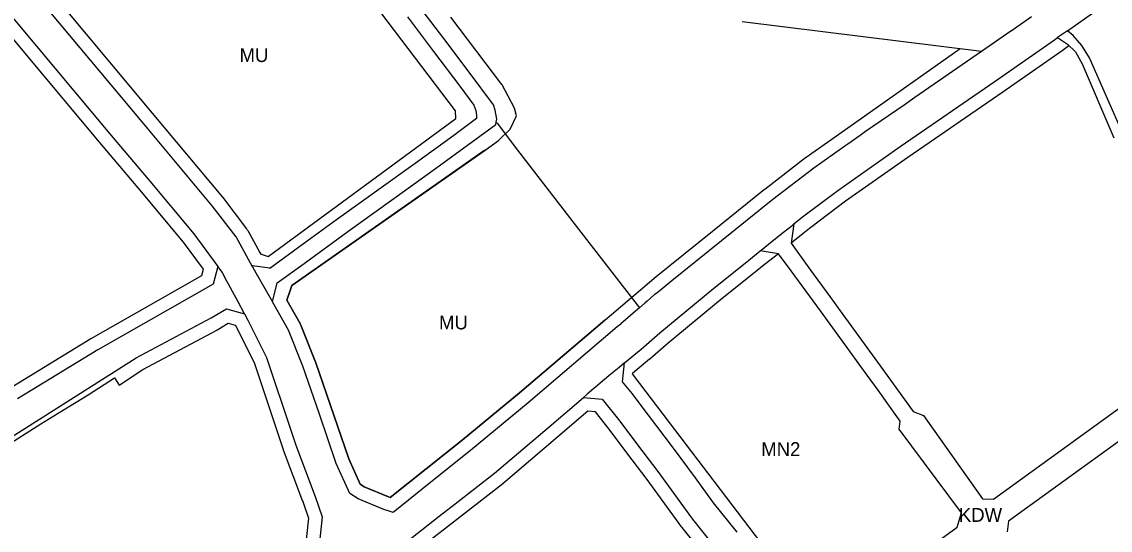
# Model space of a CAD drawing. Extents: x 7435758 to 7439981, y 5550649 to 5554049.
# Drawn here: x 7437442.5 to 7437850.9, y 5551768.7 to 5551959.4 of the extents above; entities that cross this region are included whole.
import ezdxf

# ---------------------------------------------------------------- set-up
doc = ezdxf.new("R2010")
doc.units = 0
for name, color, linetype in [('linie_rozgraniczające', 7, 'Continuous'), ('linie_zabudowy_nieprzekraczalne', 7, 'Continuous'), ('oznaczenia_przeznaczen', 7, 'Continuous')]:
    doc.layers.add(name, color=color, linetype=linetype)

msp = doc.modelspace()

# ---------------------------------------------------------------- linework, layer by layer
at = {"layer": 'linie_rozgraniczające'}
for p, q in [((7437419.08, 5551984.95), (7437448.05, 5551950.24)), ((7437487.61, 5551921.9), (7437448.82, 5551968.35)), ((7437600.85, 5551953.15), (7437589.82, 5551967.73)), ((7437834.89, 5551956.1), (7437850.63, 5551967.13)), ((7437587.18, 5551961.33), (7437596.99, 5551948.29)), ((7437802.61, 5551948.27), (7437712.83, 5551959.48)), ((7437821.43, 5551961.32), (7437813.73, 5551955.92)), ((7437813.65, 5551955.89), (7437802.61, 5551948.27)), ((7437813.66, 5551955.87), (7437813.65, 5551955.89)), ((7437813.73, 5551955.92), (7437813.66, 5551955.87)), ((7437834.89, 5551956.1), (7437831.21, 5551953.52)), ((7437837.03, 5551954.33), (7437834.89, 5551956.1)), ((7437610.36, 5551940.5), (7437600.85, 5551953.15)), ((7437807.74, 5551937.2), (7437830.01, 5551952.68)), ((7437830.01, 5551952.68), (7437830.04, 5551952.7)), ((7437830.04, 5551952.7), (7437831.21, 5551953.52)), ((7437831.21, 5551953.52), (7437834.97, 5551951.01)), ((7437834.97, 5551951.01), (7437837.94, 5551948.15)), ((7437840.29, 5551950.48), (7437837.03, 5551954.33)), ((7437448.05, 5551950.24), (7437475.42, 5551917.5)), ((7437596.99, 5551948.29), (7437606.8, 5551935.23)), ((7437802.61, 5551948.27), (7437777.58, 5551930.98)), ((7437837.94, 5551948.15), (7437840.36, 5551943.66)), ((7437843.13, 5551945.94), (7437840.29, 5551950.48)), ((7437840.36, 5551943.66), (7437852.28, 5551915.86)), ((7437855.94, 5551916.89), (7437843.13, 5551945.94)), ((7437619.5, 5551928.3), (7437610.36, 5551940.5)), ((7437606.8, 5551935.23), (7437612.15, 5551928.12)), ((7437772.17, 5551912.67), (7437807.74, 5551937.2)), ((7437777.58, 5551930.98), (7437773.57, 5551928.21)), ((7437612.15, 5551928.12), (7437612.9, 5551926.14)), ((7437620.15, 5551926.28), (7437619.5, 5551928.3)), ((7437773.57, 5551928.21), (7437759.14, 5551918.25)), ((7437613.15, 5551923.09), (7437604.55, 5551916.8)), ((7437612.9, 5551926.14), (7437613.06, 5551924.23)), ((7437613.06, 5551924.23), (7437613.15, 5551923.09)), ((7437620.7, 5551922.95), (7437620.15, 5551926.28)), ((7437620.55, 5551921.83), (7437620.7, 5551922.95)), ((7437513.95, 5551890.43), (7437487.61, 5551921.9)), ((7437597.68, 5551904.41), (7437620.42, 5551920.86)), ((7437620.42, 5551920.86), (7437620.55, 5551921.83)), ((7437620.55, 5551921.83), (7437620.98, 5551921.26)), ((7437620.98, 5551921.26), (7437627.25, 5551912.88)), ((7437759.14, 5551918.25), (7437757.12, 5551916.83)), ((7437475.42, 5551917.5), (7437489.95, 5551900.35)), ((7437604.55, 5551916.8), (7437590.08, 5551906.33)), ((7437757.12, 5551916.83), (7437752.5, 5551913.57)), ((7437627.25, 5551912.88), (7437651.38, 5551881.6)), ((7437751.4, 5551912.79), (7437739.68, 5551904.52)), ((7437748.7, 5551896.2), (7437772.17, 5551912.67)), ((7437752.15, 5551913.32), (7437751.4, 5551912.79)), ((7437752.5, 5551913.57), (7437752.15, 5551913.32)), ((7437590.08, 5551906.33), (7437576.52, 5551896.53)), ((7437581.25, 5551892.54), (7437597.68, 5551904.41)), ((7437739.68, 5551904.52), (7437724.32, 5551892.73)), ((7437489.95, 5551900.35), (7437507.05, 5551879.89)), ((7437576.52, 5551896.53), (7437560.63, 5551885.1)), ((7437735.5, 5551886.21), (7437748.7, 5551896.2)), ((7437522.88, 5551878.75), (7437513.95, 5551890.43)), ((7437564.88, 5551880.71), (7437581.25, 5551892.54)), ((7437724.32, 5551892.73), (7437685.84, 5551861.8)), ((7437732.24, 5551883.6), (7437735.5, 5551886.21)), ((7437560.63, 5551885.1), (7437548.22, 5551876.11)), ((7437651.38, 5551881.6), (7437674.25, 5551852.12)), ((7437728.36, 5551880.49), (7437731.52, 5551883.02)), ((7437732.24, 5551883.6), (7437731.24, 5551876.4)), ((7437731.52, 5551883.02), (7437732.24, 5551883.6)), ((7437507.05, 5551879.89), (7437516.05, 5551867.64)), ((7437529.07, 5551867.54), (7437522.88, 5551878.75)), ((7437548.38, 5551868.77), (7437564.88, 5551880.71)), ((7437723.47, 5551876.58), (7437728.36, 5551880.49)), ((7437548.22, 5551876.11), (7437535.57, 5551866.91)), ((7437714.52, 5551869.41), (7437719.6, 5551873.48)), ((7437719.6, 5551873.48), (7437720.62, 5551874.3)), ((7437726.51, 5551872.44), (7437719.6, 5551873.48)), ((7437720.62, 5551874.3), (7437723.47, 5551876.58)), ((7437731.24, 5551876.4), (7437738.41, 5551866.24)), ((7437702.19, 5551859.51), (7437714.52, 5551869.41)), ((7437731.2, 5551866.04), (7437726.51, 5551872.44)), ((7437516.05, 5551867.64), (7437514.27, 5551860.98)), ((7437517.73, 5551865.36), (7437516.05, 5551867.64)), ((7437518.71, 5551863.51), (7437517.73, 5551865.36)), ((7437535.56, 5551866.97), (7437528.99, 5551867.9)), ((7437528.99, 5551867.9), (7437529.07, 5551867.54)), ((7437529.07, 5551867.54), (7437530.96, 5551864.1)), ((7437535.57, 5551866.91), (7437535.56, 5551866.97)), ((7437538.33, 5551861.5), (7437548.38, 5551868.77)), ((7437742.22, 5551851.01), (7437731.2, 5551866.04)), ((7437738.41, 5551866.24), (7437745.69, 5551856.39)), ((7437514.27, 5551860.98), (7437470.98, 5551836.32)), ((7437523.62, 5551854.32), (7437518.71, 5551863.51)), ((7437530.96, 5551864.1), (7437531.18, 5551863.72)), ((7437531.18, 5551863.72), (7437534.16, 5551858.48)), ((7437536.52, 5551854.31), (7437538.33, 5551861.5)), ((7437685.84, 5551861.8), (7437681.99, 5551858.68)), ((7437534.16, 5551858.48), (7437536.52, 5551854.31)), ((7437679.84, 5551856.95), (7437677.13, 5551854.61)), ((7437679.98, 5551857.06), (7437679.84, 5551856.95)), ((7437680.88, 5551857.78), (7437679.98, 5551857.06)), ((7437681.99, 5551858.68), (7437680.88, 5551857.78)), ((7437681.86, 5551842.68), (7437702.19, 5551859.51)), ((7437525.99, 5551849.86), (7437523.62, 5551854.32)), ((7437542.53, 5551843.74), (7437536.52, 5551854.31)), ((7437676.47, 5551854.04), (7437674.25, 5551852.12)), ((7437677.13, 5551854.61), (7437676.47, 5551854.04)), ((7437745.69, 5551856.39), (7437750.65, 5551849.65)), ((7437513.52, 5551848.32), (7437519.26, 5551851.73)), ((7437519.26, 5551851.73), (7437525.99, 5551849.86)), ((7437525.99, 5551849.86), (7437527.24, 5551847.52)), ((7437670.89, 5551849.23), (7437667.25, 5551846.09)), ((7437671.9, 5551850.1), (7437670.89, 5551849.23)), ((7437674.25, 5551852.12), (7437671.9, 5551850.1)), ((7437742.22, 5551851), (7437742.22, 5551851.01)), ((7437751.47, 5551838.2), (7437742.22, 5551851)), ((7437750.65, 5551849.65), (7437764.61, 5551830.36)), ((7437485.44, 5551833.4), (7437513.52, 5551848.32)), ((7437527.24, 5551847.52), (7437534.32, 5551833.48)), ((7437665.96, 5551844.96), (7437632.46, 5551816.42)), ((7437667.24, 5551846.05), (7437665.96, 5551844.96)), ((7437667.25, 5551846.05), (7437667.24, 5551846.05)), ((7437667.25, 5551846.09), (7437667.25, 5551846.05)), ((7437547.96, 5551830.29), (7437542.53, 5551843.74)), ((7437674.9, 5551836.66), (7437681.86, 5551842.68)), ((7437668.66, 5551831.46), (7437674.9, 5551836.66)), ((7437758.35, 5551828.7), (7437751.47, 5551838.2)), ((7437426.54, 5551796.11), (7437485.44, 5551833.4)), ((7437470.98, 5551836.32), (7437440.82, 5551817.99)), ((7437534.32, 5551833.48), (7437543.64, 5551805.43)), ((7437554.15, 5551812.23), (7437547.96, 5551830.29)), ((7437666.62, 5551829.76), (7437664.79, 5551828.24)), ((7437668.66, 5551831.46), (7437666.62, 5551829.76)), ((7437667.96, 5551824.32), (7437668.66, 5551831.46)), ((7437763.84, 5551821.23), (7437758.35, 5551828.7)), ((7437764.61, 5551830.36), (7437776.99, 5551813.28)), ((7437662.82, 5551826.59), (7437659.51, 5551823.84)), ((7437664.79, 5551828.24), (7437662.82, 5551826.59)), ((7437671.6, 5551819.82), (7437667.96, 5551824.32)), ((7437807.11, 5551780.31), (7437871.35, 5551826.92)), ((7437657.13, 5551821.81), (7437654.66, 5551819.7)), ((7437658.48, 5551822.96), (7437657.13, 5551821.81)), ((7437659.51, 5551823.84), (7437658.48, 5551822.96)), ((7437770.29, 5551812.25), (7437763.84, 5551821.23)), ((7437632.46, 5551816.42), (7437610.86, 5551798.55)), ((7437640.35, 5551807.5), (7437653.28, 5551818.53)), ((7437654.66, 5551819.7), (7437653.28, 5551818.53)), ((7437653.28, 5551818.53), (7437660.32, 5551817.86)), ((7437660.32, 5551817.86), (7437666.39, 5551810.24)), ((7437674.59, 5551815.98), (7437671.6, 5551819.82)), ((7437877.2, 5551818.71), (7437812.75, 5551772.12)), ((7437560.51, 5551793.7), (7437554.15, 5551812.23)), ((7437687.04, 5551799.53), (7437674.59, 5551815.98)), ((7437772.17, 5551809.6), (7437770.29, 5551812.25)), ((7437776.99, 5551813.28), (7437780.9, 5551811.67)), ((7437666.39, 5551810.24), (7437675.56, 5551798.13)), ((7437771.76, 5551806.62), (7437772.17, 5551809.6)), ((7437780.9, 5551811.67), (7437803.06, 5551780.46)), ((7437543.64, 5551805.43), (7437545.26, 5551800.57)), ((7437619.9, 5551790.06), (7437640.35, 5551807.5)), ((7437795.17, 5551775.15), (7437771.76, 5551806.62)), ((7437545.26, 5551800.57), (7437552.55, 5551781.33)), ((7437610.86, 5551798.55), (7437598.45, 5551788.66)), ((7437675.56, 5551798.13), (7437681.15, 5551790.72)), ((7437695.36, 5551788.35), (7437687.04, 5551799.53)), ((7437565.52, 5551782.51), (7437560.51, 5551793.7)), ((7437598.45, 5551788.66), (7437581.81, 5551775.39)), ((7437605.15, 5551778.62), (7437619.9, 5551790.06)), ((7437681.15, 5551790.72), (7437692.85, 5551774.66)), ((7437702.04, 5551778.99), (7437695.36, 5551788.35)), ((7437552.55, 5551781.33), (7437555.16, 5551773.75)), ((7437568.68, 5551780.51), (7437565.52, 5551782.51)), ((7437578.38, 5551776.45), (7437568.68, 5551780.51)), ((7437803.06, 5551780.46), (7437807.11, 5551780.31)), ((7437580.32, 5551775.85), (7437578.38, 5551776.45)), ((7437581.81, 5551775.39), (7437580.32, 5551775.85)), ((7437599.12, 5551773.94), (7437605.15, 5551778.62)), ((7437710.94, 5551767.9), (7437702.04, 5551778.99)), ((7437555.16, 5551773.75), (7437552.52, 5551748.9)), ((7437588.51, 5551765.64), (7437599.12, 5551773.94)), ((7437692.85, 5551774.66), (7437694.15, 5551772.85)), ((7437694.15, 5551772.85), (7437694.43, 5551772.51)), ((7437694.43, 5551772.51), (7437694.7, 5551772.16)), ((7437694.7, 5551772.16), (7437697.09, 5551769.19)), ((7437793.51, 5551769.78), (7437795.17, 5551775.15)), ((7437812.75, 5551772.12), (7437812.29, 5551768.05)), ((7437697.09, 5551769.19), (7437701.61, 5551763.54)), ((7437740.84, 5551731.77), (7437793.51, 5551769.78))]:
    msp.add_line(p, q, dxfattribs=at)
at = {"layer": 'linie_zabudowy_nieprzekraczalne'}
for p, q in [((7437543.84, 5551860.45), (7437616.32, 5551911.33)), ((7437541.94, 5551855.04), (7437543.17, 5551858.56)), ((7437543.17, 5551858.56), (7437543.84, 5551860.45)), ((7437541.91, 5551854.96), (7437541.94, 5551855.04)), ((7437546.88, 5551846.21), (7437541.91, 5551854.96)), ((7437546.92, 5551846.13), (7437546.88, 5551846.21)), ((7437547.07, 5551845.84), (7437546.92, 5551846.13)), ((7437547.17, 5551845.61), (7437547.07, 5551845.84)), ((7437552.59, 5551832.16), (7437547.17, 5551845.61)), ((7437661.22, 5551847.49), (7437629.25, 5551820.25)), ((7437552.62, 5551832.09), (7437552.59, 5551832.16)), ((7437552.69, 5551831.91), (7437552.62, 5551832.09)), ((7437565.16, 5551795.53), (7437552.69, 5551831.91)), ((7437629.25, 5551820.25), (7437607.71, 5551802.43)), ((7437607.71, 5551802.43), (7437580.76, 5551780.95)), ((7437569.47, 5551785.93), (7437565.16, 5551795.53)), ((7437571, 5551784.96), (7437569.47, 5551785.93)), ((7437580.08, 5551781.16), (7437571, 5551784.96)), ((7437580.76, 5551780.95), (7437580.08, 5551781.16))]:
    msp.add_line(p, q, dxfattribs=at)
for points in [[(7437433.34, 5551819.29), (7437468.39, 5551840.59), (7437468.51, 5551840.66), (7437509.98, 5551864.29), (7437510.6, 5551866.62), (7437503.12, 5551876.81), (7437486.12, 5551897.13), (7437471.61, 5551914.27), (7437471.58, 5551914.3), (7437444.22, 5551947.04), (7437444.22, 5551947.04), (7437414.28, 5551982.9)], [(7437450.09, 5551974.62), (7437491.45, 5551925.11), (7437517.78, 5551893.63), (7437517.79, 5551893.63), (7437517.92, 5551893.46), (7437526.85, 5551881.78), (7437526.93, 5551881.69), (7437527.11, 5551881.42), (7437527.26, 5551881.16), (7437531.84, 5551872.87), (7437532.2, 5551872.23), (7437532.3, 5551872.2), (7437534.97, 5551871.39), (7437605.41, 5551923.13), (7437605.29, 5551925.97), (7437605.29, 5551926.09), (7437569.67, 5551972.95)], [(7437616.32, 5551911.33), (7437621.41, 5551914.9), (7437625.71, 5551919.12), (7437628.13, 5551924.17), (7437627.38, 5551927.03), (7437622.72, 5551935.79), (7437622.67, 5551935.85), (7437603.54, 5551961.13)], [(7437616.27, 5551911.29), (7437543.84, 5551860.45), (7437543.17, 5551858.56), (7437541.94, 5551855.04), (7437541.91, 5551854.96), (7437546.88, 5551846.21), (7437546.92, 5551846.13), (7437547.07, 5551845.84), (7437547.17, 5551845.61), (7437552.59, 5551832.16), (7437552.62, 5551832.09), (7437552.69, 5551831.91), (7437565.16, 5551795.53), (7437569.47, 5551785.93), (7437571, 5551784.96), (7437580.08, 5551781.16), (7437580.76, 5551780.95), (7437607.71, 5551802.43), (7437629.25, 5551820.25), (7437661.22, 5551847.49), (7437661.27, 5551847.53), (7437680.48, 5551863.89), (7437701.66, 5551880.93), (7437721.18, 5551896.63), (7437721.27, 5551896.7), (7437736.63, 5551908.49), (7437736.73, 5551908.57), (7437736.8, 5551908.61), (7437748.24, 5551916.68), (7437794.67, 5551949.43)], [(7437835.42, 5551950.37), (7437832.87, 5551948.58), (7437832.86, 5551948.57), (7437810.59, 5551933.09), (7437810.58, 5551933.08), (7437775.02, 5551908.57), (7437751.64, 5551892.16), (7437738.57, 5551882.27), (7437736.92, 5551880.95), (7437731.24, 5551876.4)], [(7437726.51, 5551872.44), (7437721.02, 5551868.21), (7437717.65, 5551865.51), (7437705.36, 5551855.64), (7437685.08, 5551838.86), (7437678.17, 5551832.88), (7437678.1, 5551832.82), (7437673.44, 5551828.94), (7437671.49, 5551827.37), (7437676.61, 5551820.64), (7437719.71, 5551764.14), (7437740.84, 5551731.77)], [(7437427.15, 5551794.29), (7437449.65, 5551808.57), (7437457.8, 5551813.65), (7437467.38, 5551819.51), (7437477.21, 5551825.88), (7437478.97, 5551823.1), (7437487.89, 5551829.04), (7437515.87, 5551843.9), (7437515.91, 5551843.93), (7437516.08, 5551844.02), (7437519.96, 5551846.33), (7437519.98, 5551846.34), (7437522.59, 5551845.62), (7437522.8, 5551845.21), (7437529.69, 5551831.56), (7437540.51, 5551798.99), (7437540.58, 5551798.79), (7437547.87, 5551779.56), (7437547.88, 5551779.53), (7437548.01, 5551779.23), (7437548.08, 5551779.1), (7437550.07, 5551773.18), (7437547.75, 5551751.39)], [(7437701.89, 5551755.2), (7437690.25, 5551769.72), (7437690.11, 5551769.9), (7437690.09, 5551769.93), (7437688.8, 5551771.73), (7437677.14, 5551787.75), (7437671.57, 5551795.12), (7437662.44, 5551807.17), (7437657.73, 5551813.08), (7437654.91, 5551813.35), (7437643.59, 5551803.69), (7437623.14, 5551786.26), (7437623.1, 5551786.22), (7437622.96, 5551786.11), (7437602.2, 5551770), (7437591.73, 5551761.81)]]:
    msp.add_lwpolyline(points, dxfattribs=at)

# ---------------------------------------------------------------- texts
at = {"layer": 'oznaczenia_przeznaczen'}
for s, p in [('MU', (7437524.19, 5551944.33)), ('MU', (7437599.06, 5551844.03)), ('MN2', (7437719.97, 5551796.52)), ('KDW', (7437794.14, 5551771.83))]:
    msp.add_text(s, height=5.2, dxfattribs=at).set_placement(p)

doc.saveas('drawing.dxf')
